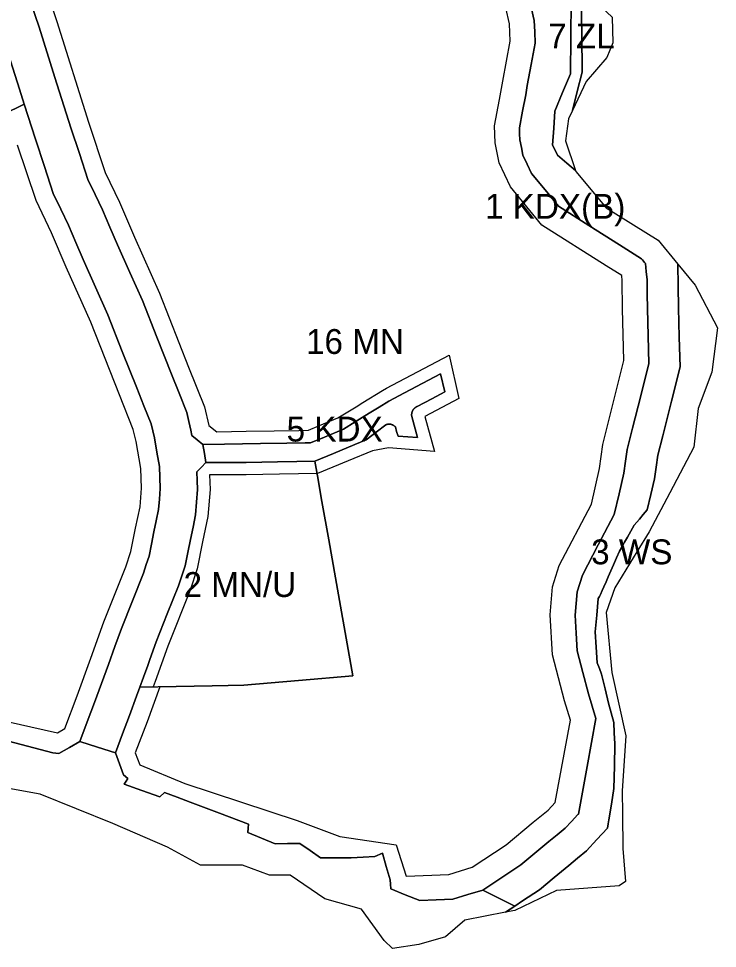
# Model space of a CAD drawing. Extents: x 7423691 to 7425475, y 5552085 to 5554331.
# Drawn here: x 7424592.3 to 7424817.1, y 5552085.5 to 5552384.7 of the extents above; entities that cross this region are included whole.
import ezdxf

# ---------------------------------------------------------------- set-up
doc = ezdxf.new("R2010")
doc.units = 0
for name, color, linetype in [('linia_zabudowy_nieprzekraczalna', 7, 'Continuous'), ('linie_rozgraniczajace', 7, 'Continuous'), ('oznaczenia_przeznaczen', 7, 'Continuous')]:
    doc.layers.add(name, color=color, linetype=linetype)

msp = doc.modelspace()

# ---------------------------------------------------------------- linework, layer by layer
at = {"layer": 'linia_zabudowy_nieprzekraczalna'}
for points in [[(7424595.08, 5552411.93), (7424604.56, 5552383.75), (7424614.78, 5552351.39), (7424620.16, 5552335.16), (7424624.75, 5552325.61), (7424629.54, 5552314.31), (7424637.6, 5552296.28), (7424646.97, 5552272.5), (7424652.11, 5552259.74), (7424653.5, 5552253.77), (7424656, 5552251.71), (7424665.48, 5552251.87), (7424674.48, 5552252.02), (7424682.47, 5552252.17), (7424685.48, 5552252.22), (7424689.12, 5552253.73), (7424695.02, 5552256.16), (7424696.05, 5552256.8), (7424700.87, 5552259.78), (7424702.97, 5552261.09), (7424709.37, 5552265.05), (7424710.63, 5552265.72), (7424730.79, 5552276.36), (7424733.95, 5552262.43), (7424722.92, 5552256.61), (7424726.03, 5552245.42), (7424711.27, 5552246.5), (7424711.27, 5552246.5), (7424706.15, 5552245.6), (7424698.34, 5552242.38), (7424688.4, 5552238.27), (7424676.15, 5552238.05), (7424665.48, 5552237.87), (7424653.69, 5552237.85), (7424653.88, 5552233.11), (7424653.18, 5552224.4), (7424651.46, 5552216.27), (7424649.71, 5552207.59)], [(7424637.68, 5552169.66), (7424633.6, 5552158.36), (7424629.8, 5552148.37), (7424631.22, 5552144.58), (7424645.73, 5552138.53), (7424681.92, 5552126.66), (7424695.57, 5552121.5), (7424713.72, 5552118.76), (7424717, 5552108.67), (7424730.64, 5552109.29), (7424738.18, 5552111.55), (7424749.09, 5552118.79), (7424757.8, 5552126.07), (7424762.63, 5552129.99), (7424764.92, 5552132.46), (7424769.8, 5552158.95), (7424767.88, 5552165.18), (7424764.07, 5552179.94), (7424763.28, 5552192.8), (7424764.06, 5552201.81), (7424766.23, 5552208.64), (7424776.53, 5552228.38), (7424779.15, 5552239.87), (7424780.23, 5552247.59), (7424787.03, 5552274.62), (7424786.55, 5552291.25), (7424786.46, 5552300.24), (7424786.3, 5552301.97), (7424781.31, 5552305.09), (7424760.6, 5552318.21), (7424750.5, 5552330.5), (7424746.87, 5552338.25), (7424745.57, 5552344.68), (7424745.35, 5552350.17), (7424747.02, 5552358.66), (7424748.06, 5552364.55), (7424750.43, 5552377.37), (7424750.2, 5552383.01), (7424748.98, 5552388.13)], [(7424551.84, 5552166.71), (7424604.77, 5552154.87), (7424607.11, 5552156.21), (7424611.09, 5552166.7), (7424615.5, 5552178.9), (7424619.71, 5552190.51), (7424626.76, 5552208.25), (7424628.41, 5552213.24), (7424629.92, 5552220.71), (7424631.36, 5552227.56), (7424631.84, 5552233.55), (7424631.58, 5552239.91), (7424630.07, 5552248.6), (7424629.16, 5552252.48), (7424624.68, 5552263.62), (7424615.47, 5552286.98), (7424607.54, 5552304.73), (7424602.88, 5552315.72), (7424597.86, 5552326.15), (7424591.95, 5552344)], [(7424649.71, 5552207.59), (7424647.45, 5552200.74), (7424640.28, 5552182.7), (7424636.19, 5552171.4), (7424635.54, 5552169.62)]]:
    msp.add_lwpolyline(points, dxfattribs=at)
at = {"layer": 'linie_rozgraniczajace'}
for points in [[(7424766.12, 5552401.43), (7424769.77, 5552397.94), (7424783.18, 5552385.11), (7424783.46, 5552376.91), (7424781.51, 5552372.14), (7424774.86, 5552364.48), (7424770.43, 5552355.08), (7424771.99, 5552361.24), (7424773.55, 5552367.39), (7424773.42, 5552379.79), (7424773.28, 5552392.2), (7424769.7, 5552396.82)], [(7424748.96, 5552097.1), (7424751.93, 5552099.07), (7424754.42, 5552100.72), (7424759.88, 5552104.34), (7424764.56, 5552108.26), (7424769.24, 5552112.18), (7424772.1, 5552114.5), (7424774.96, 5552116.81), (7424778.35, 5552120.47), (7424781.74, 5552124.13), (7424781.97, 5552125.5), (7424782.2, 5552126.87), (7424783, 5552131.91), (7424783.81, 5552136.94), (7424783.94, 5552144.14), (7424784.06, 5552151.34), (7424783.92, 5552154.78), (7424783.78, 5552158.21), (7424782.94, 5552161.3), (7424782.1, 5552164.4), (7424780.93, 5552169.04), (7424779.76, 5552173.68), (7424779.11, 5552175.51), (7424778.45, 5552177.33), (7424778.09, 5552182.35), (7424777.72, 5552187.36), (7424778.25, 5552192.7), (7424778.78, 5552198.04), (7424779.15, 5552198.69), (7424779.51, 5552199.34), (7424780.04, 5552200.6), (7424780.56, 5552201.86), (7424781.25, 5552203.46), (7424781.94, 5552205.05), (7424782.77, 5552206.96), (7424783.61, 5552208.87), (7424784.59, 5552211.1), (7424785.58, 5552213.33), (7424786.31, 5552214.61), (7424787.22, 5552216.21), (7424788.14, 5552217.81), (7424789.25, 5552219.73), (7424790.36, 5552221.65), (7424791.17, 5552222.62), (7424791.99, 5552223.59), (7424793.23, 5552225.08), (7424794.48, 5552226.56), (7424795.67, 5552231.55), (7424796.86, 5552236.54), (7424797.39, 5552240.34), (7424797.92, 5552244.14), (7424799.51, 5552250.46), (7424802.3, 5552261.55), (7424805.09, 5552272.64), (7424804.82, 5552282.12), (7424804.55, 5552291.6), (7424804.47, 5552298.62), (7424804.4, 5552305.63), (7424809.99, 5552298.89), (7424817.09, 5552285.18), (7424815.33, 5552270.93), (7424810.92, 5552259.2), (7424809.54, 5552246.79), (7424801.81, 5552232.03), (7424795.09, 5552219.56), (7424791.12, 5552213.07), (7424784.07, 5552201.45), (7424781.31, 5552193.51), (7424783.14, 5552174.2), (7424787.64, 5552153.84), (7424786.45, 5552136.13), (7424786.51, 5552128.62), (7424786.62, 5552117.66), (7424787.54, 5552106.97), (7424785.44, 5552105.61), (7424765.27, 5552104.07), (7424751.93, 5552097.69)], [(7424631.26, 5552169.54), (7424632.43, 5552172.77), (7424633.79, 5552176.53), (7424634.49, 5552178.44), (7424636.54, 5552184.12), (7424640.11, 5552193.11), (7424643.69, 5552202.1), (7424644.76, 5552205.36), (7424645.83, 5552208.61), (7424646.69, 5552212.84), (7424647.55, 5552217.07), (7424648.38, 5552221.02), (7424649.21, 5552224.98), (7424649.54, 5552229.08), (7424649.87, 5552233.19), (7424649.76, 5552236.02), (7424649.64, 5552238.84), (7424651.08, 5552240.34), (7424652.52, 5552241.84), (7424653.52, 5552241.85), (7424656.02, 5552241.85), (7424658.95, 5552241.86), (7424665.44, 5552241.87), (7424675.52, 5552242.04), (7424681.83, 5552242.16), (7424687.57, 5552242.26), (7424688.41, 5552237.51), (7424689.87, 5552229.28), (7424692.04, 5552216.97), (7424694.22, 5552204.66), (7424695.51, 5552197.37), (7424697.65, 5552185.26), (7424699.79, 5552173.15), (7424682.27, 5552171.67), (7424664.75, 5552170.2), (7424659.65, 5552170.1), (7424654.56, 5552169.99), (7424642.91, 5552169.77)]]:
    msp.add_lwpolyline(points, close=True, dxfattribs=at)
for points in [[(7424594.07, 5552396.11), (7424598.86, 5552381.89), (7424603.97, 5552365.71), (7424609.08, 5552349.54), (7424611.83, 5552341.22), (7424614.58, 5552332.91), (7424616.93, 5552328.02), (7424619.28, 5552323.14), (7424621.66, 5552317.53), (7424624.04, 5552311.91), (7424628.06, 5552302.93), (7424632.07, 5552293.96), (7424636.73, 5552282.12), (7424641.4, 5552270.28), (7424643.88, 5552264.1), (7424646.37, 5552257.92), (7424647.04, 5552255.06), (7424647.37, 5552253.66), (7424647.71, 5552252.2), (7424648, 5552250.53), (7424649.76, 5552249.08), (7424651.52, 5552247.63), (7424652.02, 5552244.74), (7424652.52, 5552241.84), (7424651.08, 5552240.34), (7424649.64, 5552238.84), (7424649.76, 5552236.02), (7424649.87, 5552233.19), (7424649.54, 5552229.08), (7424649.21, 5552224.98), (7424648.38, 5552221.02), (7424647.55, 5552217.07), (7424646.69, 5552212.84), (7424645.83, 5552208.61), (7424644.76, 5552205.36), (7424643.69, 5552202.1), (7424640.11, 5552193.11), (7424636.54, 5552184.12), (7424634.49, 5552178.44), (7424633.79, 5552176.53), (7424632.43, 5552172.77), (7424631.26, 5552169.54), (7424630.2, 5552166.61), (7424627.97, 5552160.45), (7424625.7, 5552154.46), (7424623.39, 5552148.38), (7424617.67, 5552150.23), (7424611.96, 5552152.07), (7424614.34, 5552158.34), (7424616.72, 5552164.62), (7424618.93, 5552170.74), (7424621.15, 5552176.85), (7424623.24, 5552182.62), (7424625.32, 5552188.38), (7424628.86, 5552197.29), (7424632.4, 5552206.2), (7424633.31, 5552208.95), (7424634.22, 5552211.7), (7424635.01, 5552215.6), (7424635.8, 5552219.5), (7424636.55, 5552223.1), (7424637.31, 5552226.7), (7424637.58, 5552230.07), (7424637.85, 5552233.43), (7424637.71, 5552236.99), (7424637.56, 5552240.56), (7424636.76, 5552245.18), (7424635.95, 5552249.8), (7424635.42, 5552252.05), (7424634.89, 5552254.3), (7424632.57, 5552260.07), (7424630.25, 5552265.84), (7424625.63, 5552277.57)], [(7424718.71, 5552257.3), (7424718.72, 5552257.41), (7424718.73, 5552257.52), (7424718.74, 5552257.62), (7424718.76, 5552257.73), (7424718.78, 5552257.84), (7424718.81, 5552257.94), (7424718.84, 5552258.04), (7424718.87, 5552258.15), (7424718.91, 5552258.25), (7424718.95, 5552258.35), (7424719, 5552258.44), (7424719.05, 5552258.54), (7424719.1, 5552258.63), (7424719.15, 5552258.73), (7424719.21, 5552258.82), (7424719.28, 5552258.9), (7424719.34, 5552258.99), (7424719.41, 5552259.07), (7424719.48, 5552259.15), (7424719.56, 5552259.23), (7424719.63, 5552259.3), (7424719.71, 5552259.38), (7424719.8, 5552259.44), (7424719.88, 5552259.51), (7424719.97, 5552259.57), (7424720.06, 5552259.63), (7424720.15, 5552259.69), (7424720.25, 5552259.74), (7424720.34, 5552259.79), (7424720.44, 5552259.83), (7424720.51, 5552259.87), (7424725.21, 5552262.34), (7424729.37, 5552264.54), (7424728.04, 5552270.39), (7424720.27, 5552266.29), (7424716.39, 5552264.24), (7424711.36, 5552261.58), (7424708.22, 5552259.63), (7424705.08, 5552257.69), (7424700.57, 5552254.89), (7424696.84, 5552252.58), (7424690.65, 5552250.03), (7424686.17, 5552248.2), (7424684.42, 5552248.2), (7424678.54, 5552248.1), (7424670.05, 5552247.95), (7424658.53, 5552247.75), (7424651.52, 5552247.63), (7424649.76, 5552249.08), (7424648, 5552250.53), (7424647.71, 5552252.2), (7424647.37, 5552253.66), (7424647.04, 5552255.06), (7424646.37, 5552257.92), (7424643.88, 5552264.1), (7424641.4, 5552270.28), (7424636.73, 5552282.12), (7424632.07, 5552293.96), (7424628.06, 5552302.93), (7424624.04, 5552311.91), (7424621.66, 5552317.53), (7424619.28, 5552323.14), (7424616.93, 5552328.02), (7424614.58, 5552332.91), (7424611.83, 5552341.22), (7424609.08, 5552349.54), (7424603.97, 5552365.71), (7424598.86, 5552381.89), (7424594.07, 5552396.11)], [(7424625.63, 5552277.57), (7424621.01, 5552289.31), (7424617.02, 5552298.21), (7424613.04, 5552307.12), (7424610.69, 5552312.66), (7424608.35, 5552318.19), (7424605.89, 5552323.3), (7424603.43, 5552328.4), (7424600.55, 5552337.13), (7424597.66, 5552345.85), (7424594.08, 5552357.17), (7424592.55, 5552362.01), (7424587.45, 5552378.17), (7424586.19, 5552381.92), (7424582.58, 5552392.65)], [(7424773.28, 5552392.2), (7424773.42, 5552379.79), (7424773.55, 5552367.39), (7424771.99, 5552361.24), (7424770.43, 5552355.08), (7424769.18, 5552352.42), (7424768.23, 5552345.3), (7424771.44, 5552335.76), (7424768.62, 5552338.2), (7424765.65, 5552340.77), (7424764.87, 5552342.35), (7424764.08, 5552343.93), (7424764.42, 5552349.41), (7424764.75, 5552354.89), (7424767.29, 5552360.92), (7424769.82, 5552366.94), (7424769.9, 5552378.7), (7424769.99, 5552390.45)], [(7424769.99, 5552390.45), (7424769.9, 5552378.7), (7424769.82, 5552366.94), (7424767.29, 5552360.92), (7424764.75, 5552354.89), (7424764.42, 5552349.41), (7424764.08, 5552343.93), (7424764.87, 5552342.35), (7424765.65, 5552340.77), (7424768.62, 5552338.2), (7424771.44, 5552335.76), (7424771.54, 5552335.48), (7424781.28, 5552323.8), (7424797.99, 5552313.35), (7424804.4, 5552305.63), (7424804.47, 5552298.62), (7424804.55, 5552291.6), (7424804.82, 5552282.12), (7424805.09, 5552272.64), (7424802.3, 5552261.55), (7424799.51, 5552250.46), (7424797.92, 5552244.14), (7424797.39, 5552240.34), (7424796.86, 5552236.54), (7424795.67, 5552231.55), (7424794.48, 5552226.56), (7424793.23, 5552225.08), (7424791.99, 5552223.59), (7424791.17, 5552222.62), (7424790.36, 5552221.65), (7424789.25, 5552219.73), (7424788.14, 5552217.81), (7424787.22, 5552216.21), (7424786.31, 5552214.61), (7424785.58, 5552213.33), (7424784.59, 5552211.1), (7424783.61, 5552208.87), (7424782.77, 5552206.96), (7424781.94, 5552205.05), (7424781.25, 5552203.46), (7424780.56, 5552201.86), (7424780.04, 5552200.6), (7424779.51, 5552199.34), (7424779.15, 5552198.69), (7424778.78, 5552198.04), (7424778.25, 5552192.7), (7424777.72, 5552187.36), (7424778.09, 5552182.35), (7424778.45, 5552177.33), (7424779.11, 5552175.51), (7424779.76, 5552173.68), (7424780.93, 5552169.04), (7424782.1, 5552164.4), (7424782.94, 5552161.3), (7424783.78, 5552158.21), (7424783.92, 5552154.78), (7424784.06, 5552151.34), (7424783.94, 5552144.14), (7424783.81, 5552136.94), (7424783, 5552131.91), (7424782.2, 5552126.87), (7424781.97, 5552125.5), (7424781.74, 5552124.13), (7424778.35, 5552120.47), (7424774.96, 5552116.81), (7424772.1, 5552114.5), (7424769.24, 5552112.18), (7424764.56, 5552108.26), (7424759.88, 5552104.34), (7424754.42, 5552100.72), (7424751.93, 5552099.07), (7424741.61, 5552104.22)], [(7424757.28, 5552387.83), (7424758.16, 5552384.1), (7424758.31, 5552380.45), (7424758.46, 5552376.79), (7424757.19, 5552369.96), (7424755.93, 5552363.12), (7424755.41, 5552360.18), (7424754.39, 5552354.87), (7424753.38, 5552349.56), (7424753.46, 5552347.6), (7424753.53, 5552345.64), (7424754.03, 5552343.21), (7424754.52, 5552340.78), (7424755.92, 5552337.79), (7424757.32, 5552334.8), (7424761.64, 5552329.54), (7424765.97, 5552324.28), (7424775.76, 5552318.08), (7424785.56, 5552311.87), (7424789.14, 5552309.64), (7424792.71, 5552307.4), (7424793.04, 5552307.01), (7424793.68, 5552306.24), (7424794, 5552305.85), (7424794.22, 5552303.24), (7424794.45, 5552300.63), (7424794.5, 5552296.02), (7424794.55, 5552291.4), (7424794.8, 5552282.57), (7424795.06, 5552273.74), (7424792.44, 5552263.32), (7424789.82, 5552252.9), (7424788.96, 5552249.48), (7424788.09, 5552246.06), (7424787.56, 5552242.23), (7424787.02, 5552238.4), (7424785.44, 5552231.77), (7424783.86, 5552225.14), (7424778.75, 5552215.34), (7424773.65, 5552205.55), (7424772.8, 5552202.89), (7424771.95, 5552200.24), (7424771.63, 5552196.47), (7424771.3, 5552192.7), (7424771.65, 5552186.95), (7424772, 5552181.19), (7424773.79, 5552174.28), (7424775.58, 5552167.36), (7424776.8, 5552163.39), (7424778.03, 5552159.43), (7424775.19, 5552144.04), (7424772.35, 5552128.65), (7424772.21, 5552128.55), (7424770.16, 5552126.34), (7424768.11, 5552124.13), (7424765.5, 5552122.02), (7424762.88, 5552119.9), (7424758.38, 5552116.13), (7424753.89, 5552112.37), (7424747.75, 5552108.3), (7424741.61, 5552104.22), (7424736.8, 5552102.78), (7424731.99, 5552101.34), (7424726.64, 5552101.1)], [(7424741.61, 5552104.22), (7424747.75, 5552108.3), (7424753.89, 5552112.37), (7424758.38, 5552116.13), (7424762.88, 5552119.9), (7424765.5, 5552122.02), (7424768.11, 5552124.13), (7424770.16, 5552126.34), (7424772.21, 5552128.55), (7424772.35, 5552128.65), (7424775.19, 5552144.04), (7424778.03, 5552159.43), (7424776.8, 5552163.39), (7424775.58, 5552167.36), (7424773.79, 5552174.28), (7424772, 5552181.19), (7424771.65, 5552186.95), (7424771.3, 5552192.7), (7424771.63, 5552196.47), (7424771.95, 5552200.24), (7424772.8, 5552202.89), (7424773.65, 5552205.55), (7424778.75, 5552215.34), (7424783.86, 5552225.14), (7424785.44, 5552231.77), (7424787.02, 5552238.4), (7424787.56, 5552242.23), (7424788.09, 5552246.06), (7424788.96, 5552249.48), (7424789.82, 5552252.9), (7424792.44, 5552263.32), (7424795.06, 5552273.74), (7424794.8, 5552282.57), (7424794.55, 5552291.4), (7424794.5, 5552296.02), (7424794.45, 5552300.63), (7424794.22, 5552303.24), (7424794, 5552305.85), (7424793.68, 5552306.24), (7424793.04, 5552307.01), (7424792.71, 5552307.4), (7424789.14, 5552309.64), (7424785.56, 5552311.87), (7424775.76, 5552318.08), (7424765.97, 5552324.28), (7424761.64, 5552329.54), (7424757.32, 5552334.8), (7424755.92, 5552337.79), (7424754.52, 5552340.78), (7424754.03, 5552343.21), (7424753.53, 5552345.64), (7424753.46, 5552347.6), (7424753.38, 5552349.56), (7424754.39, 5552354.87), (7424755.41, 5552360.18), (7424755.93, 5552363.12), (7424757.19, 5552369.96), (7424758.46, 5552376.79), (7424758.31, 5552380.45), (7424758.16, 5552384.1), (7424757.28, 5552387.83)], [(7424587.45, 5552378.17), (7424592.55, 5552362.01), (7424594.08, 5552357.17), (7424580.69, 5552350.62)], [(7424580.69, 5552350.62), (7424594.08, 5552357.17), (7424597.66, 5552345.85), (7424600.55, 5552337.13), (7424603.43, 5552328.4), (7424605.89, 5552323.3), (7424608.35, 5552318.19), (7424610.69, 5552312.66), (7424613.04, 5552307.12), (7424617.02, 5552298.21), (7424621.01, 5552289.31), (7424625.63, 5552277.57), (7424630.25, 5552265.84), (7424632.57, 5552260.07), (7424634.89, 5552254.3), (7424635.42, 5552252.05), (7424635.95, 5552249.8), (7424636.76, 5552245.18), (7424637.56, 5552240.56), (7424637.71, 5552236.99), (7424637.85, 5552233.43), (7424637.58, 5552230.07), (7424637.31, 5552226.7), (7424636.55, 5552223.1), (7424635.8, 5552219.5), (7424635.01, 5552215.6), (7424634.22, 5552211.7), (7424633.31, 5552208.95), (7424632.4, 5552206.2), (7424628.86, 5552197.29), (7424625.32, 5552188.38), (7424623.24, 5552182.62), (7424621.15, 5552176.85), (7424618.93, 5552170.74), (7424616.72, 5552164.62), (7424614.34, 5552158.34), (7424611.96, 5552152.07), (7424608.6, 5552150.15), (7424605.25, 5552148.23), (7424603.28, 5552148.39), (7424595.13, 5552150.56), (7424586.99, 5552152.73)], [(7424651.52, 5552247.63), (7424658.53, 5552247.75), (7424670.05, 5552247.95), (7424678.54, 5552248.1), (7424684.42, 5552248.2), (7424686.17, 5552248.2), (7424690.65, 5552250.03), (7424696.84, 5552252.58), (7424700.57, 5552254.89), (7424705.08, 5552257.69), (7424708.22, 5552259.63), (7424711.36, 5552261.58), (7424716.39, 5552264.24), (7424720.27, 5552266.29), (7424728.04, 5552270.39), (7424729.37, 5552264.54), (7424725.21, 5552262.34), (7424720.51, 5552259.87), (7424720.44, 5552259.83), (7424720.34, 5552259.79), (7424720.25, 5552259.74), (7424720.15, 5552259.69), (7424720.06, 5552259.63), (7424719.97, 5552259.57), (7424719.88, 5552259.51), (7424719.8, 5552259.44), (7424719.71, 5552259.38), (7424719.63, 5552259.3), (7424719.56, 5552259.23), (7424719.48, 5552259.15), (7424719.41, 5552259.07), (7424719.34, 5552258.99), (7424719.28, 5552258.9), (7424719.21, 5552258.82), (7424719.15, 5552258.73), (7424719.1, 5552258.63), (7424719.05, 5552258.54), (7424719, 5552258.44), (7424718.95, 5552258.35), (7424718.91, 5552258.25), (7424718.87, 5552258.15), (7424718.84, 5552258.04), (7424718.81, 5552257.94), (7424718.78, 5552257.84), (7424718.76, 5552257.73), (7424718.74, 5552257.62), (7424718.73, 5552257.52), (7424718.72, 5552257.41), (7424718.71, 5552257.3), (7424718.71, 5552257.2), (7424718.71, 5552257.09), (7424718.72, 5552256.98), (7424718.73, 5552256.87), (7424718.74, 5552256.77), (7424718.76, 5552256.66), (7424720.65, 5552249.82), (7424717.49, 5552250.06), (7424714.33, 5552250.29), (7424713.89, 5552251.77), (7424713.47, 5552253.26), (7424713.44, 5552253.3), (7424713.37, 5552253.37), (7424713.29, 5552253.44), (7424713.22, 5552253.51), (7424713.14, 5552253.58), (7424713.06, 5552253.64), (7424712.97, 5552253.71), (7424712.89, 5552253.76), (7424712.8, 5552253.82), (7424712.71, 5552253.87), (7424712.62, 5552253.91), (7424712.52, 5552253.96), (7424712.43, 5552254), (7424712.33, 5552254.03), (7424712.23, 5552254.06), (7424712.13, 5552254.09), (7424712.03, 5552254.12), (7424711.93, 5552254.14), (7424711.83, 5552254.15), (7424711.73, 5552254.17), (7424711.63, 5552254.17), (7424711.52, 5552254.18), (7424711.42, 5552254.18), (7424711.32, 5552254.18), (7424711.21, 5552254.17), (7424711.11, 5552254.16), (7424711.01, 5552254.14), (7424710.91, 5552254.12), (7424710.81, 5552254.1), (7424710.71, 5552254.07), (7424710.61, 5552254.04), (7424710.51, 5552254.01), (7424710.42, 5552253.97), (7424707.31, 5552251.56), (7424704.13, 5552249.1), (7424700.47, 5552247.59), (7424693.53, 5552244.72), (7424687.57, 5552242.26), (7424681.83, 5552242.16), (7424675.52, 5552242.04)], [(7424726.64, 5552101.1), (7424721.3, 5552100.86), (7424716.66, 5552102.75), (7424712.03, 5552104.63), (7424711.92, 5552106.08), (7424711.8, 5552107.53), (7424710.56, 5552111.84), (7424709.31, 5552116.14), (7424706.88, 5552115.07), (7424703.07, 5552114.82), (7424699.26, 5552114.56), (7424697.37, 5552114.58), (7424695.48, 5552114.6), (7424692.42, 5552114.62), (7424689.37, 5552114.65), (7424686.06, 5552116.93), (7424682.76, 5552119.2), (7424678.8, 5552119.18), (7424674.84, 5552119.16), (7424670.45, 5552120.97), (7424666.06, 5552122.78), (7424666.17, 5552124.1), (7424666.28, 5552125.41), (7424656.87, 5552128.96), (7424647.45, 5552132.52), (7424643.31, 5552134.09), (7424639.17, 5552135.65), (7424637.68, 5552134.24), (7424631.95, 5552136.29), (7424626.21, 5552138.33), (7424626.82, 5552139.25), (7424627.42, 5552140.16), (7424626.03, 5552141.35), (7424623.39, 5552148.38), (7424625.7, 5552154.46), (7424627.97, 5552160.45), (7424630.2, 5552166.61), (7424631.26, 5552169.54), (7424642.91, 5552169.77), (7424654.56, 5552169.99), (7424659.65, 5552170.1), (7424664.75, 5552170.2), (7424682.27, 5552171.67), (7424699.79, 5552173.15), (7424697.65, 5552185.26), (7424695.51, 5552197.37), (7424694.22, 5552204.66), (7424692.04, 5552216.97), (7424689.87, 5552229.28), (7424688.41, 5552237.51), (7424687.57, 5552242.26), (7424693.53, 5552244.72), (7424700.47, 5552247.59), (7424704.13, 5552249.1), (7424707.31, 5552251.56), (7424710.42, 5552253.97), (7424710.51, 5552254.01), (7424710.61, 5552254.04), (7424710.71, 5552254.07), (7424710.81, 5552254.1), (7424710.91, 5552254.12), (7424711.01, 5552254.14), (7424711.11, 5552254.16), (7424711.21, 5552254.17), (7424711.32, 5552254.18), (7424711.42, 5552254.18), (7424711.52, 5552254.18), (7424711.63, 5552254.17), (7424711.73, 5552254.17), (7424711.83, 5552254.15), (7424711.93, 5552254.14), (7424712.03, 5552254.12), (7424712.13, 5552254.09), (7424712.23, 5552254.06), (7424712.33, 5552254.03), (7424712.43, 5552254), (7424712.52, 5552253.96), (7424712.62, 5552253.91), (7424712.71, 5552253.87), (7424712.8, 5552253.82), (7424712.89, 5552253.76), (7424712.97, 5552253.71), (7424713.06, 5552253.64), (7424713.14, 5552253.58), (7424713.22, 5552253.51), (7424713.29, 5552253.44), (7424713.37, 5552253.37), (7424713.44, 5552253.3), (7424713.47, 5552253.26), (7424713.89, 5552251.77), (7424714.33, 5552250.29), (7424717.49, 5552250.06), (7424720.65, 5552249.82), (7424718.76, 5552256.66), (7424718.74, 5552256.77), (7424718.73, 5552256.87), (7424718.72, 5552256.98), (7424718.71, 5552257.09), (7424718.71, 5552257.2), (7424718.71, 5552257.3)], [(7424675.52, 5552242.04), (7424665.44, 5552241.87), (7424658.95, 5552241.86), (7424656.02, 5552241.85), (7424653.52, 5552241.85), (7424652.52, 5552241.84), (7424652.02, 5552244.74), (7424651.52, 5552247.63)], [(7424586.99, 5552152.73), (7424595.13, 5552150.56), (7424603.28, 5552148.39), (7424605.25, 5552148.23), (7424608.6, 5552150.15), (7424611.96, 5552152.07), (7424617.67, 5552150.23), (7424623.39, 5552148.38), (7424626.03, 5552141.35), (7424627.42, 5552140.16), (7424626.82, 5552139.25), (7424626.21, 5552138.33), (7424631.95, 5552136.29), (7424637.68, 5552134.24), (7424639.17, 5552135.65), (7424643.31, 5552134.09), (7424647.45, 5552132.52), (7424656.87, 5552128.96), (7424666.28, 5552125.41), (7424666.17, 5552124.1), (7424666.06, 5552122.78), (7424670.45, 5552120.97), (7424674.84, 5552119.16), (7424678.8, 5552119.18), (7424682.76, 5552119.2), (7424686.06, 5552116.93), (7424689.37, 5552114.65), (7424692.42, 5552114.62), (7424695.48, 5552114.6), (7424697.37, 5552114.58), (7424699.26, 5552114.56), (7424703.07, 5552114.82), (7424706.88, 5552115.07), (7424709.31, 5552116.14), (7424710.56, 5552111.84), (7424711.8, 5552107.53), (7424711.92, 5552106.08), (7424712.03, 5552104.63), (7424716.66, 5552102.75), (7424721.3, 5552100.86), (7424726.64, 5552101.1), (7424731.99, 5552101.34), (7424736.8, 5552102.78), (7424741.61, 5552104.22), (7424751.93, 5552099.07), (7424748.96, 5552097.1), (7424735.79, 5552094.51), (7424729.63, 5552089.19), (7424720.98, 5552086.7), (7424712.54, 5552085.46), (7424709.88, 5552088.03), (7424702.59, 5552098.1), (7424690.76, 5552101.36), (7424679.62, 5552109.03), (7424673, 5552109), (7424664.3, 5552112.25)], [(7424664.3, 5552112.25), (7424650.8, 5552112.27), (7424640.17, 5552118.07), (7424622.53, 5552125.65), (7424599.18, 5552135.12), (7424567.14, 5552140.87), (7424549.35, 5552146.45), (7424531.46, 5552149.64), (7424517.45, 5552149.68), (7424490.76, 5552145.07), (7424487.25, 5552143.48), (7424470.4, 5552135.88), (7424457.35, 5552124.46), (7424449.66, 5552109.7), (7424443.85, 5552093.75), (7424440.45, 5552095.75), (7424427.06, 5552103.61)]]:
    msp.add_lwpolyline(points, dxfattribs=at)

# ---------------------------------------------------------------- texts
at = {"layer": 'oznaczenia_przeznaczen'}
for s, p in [('7 ZL', (7424762.63, 5552375.09)), ('1 KDX(B)', (7424742.31, 5552320.27)), ('16 MN', (7424684.72, 5552276.76)), ('5 KDX', (7424678.48, 5552248.58)), ('3 WS', (7424776.47, 5552209.07)), ('2 MN/U', (7424645.32, 5552198.55))]:
    msp.add_text(s, height=8, dxfattribs=at).set_placement(p)

doc.saveas('drawing.dxf')
